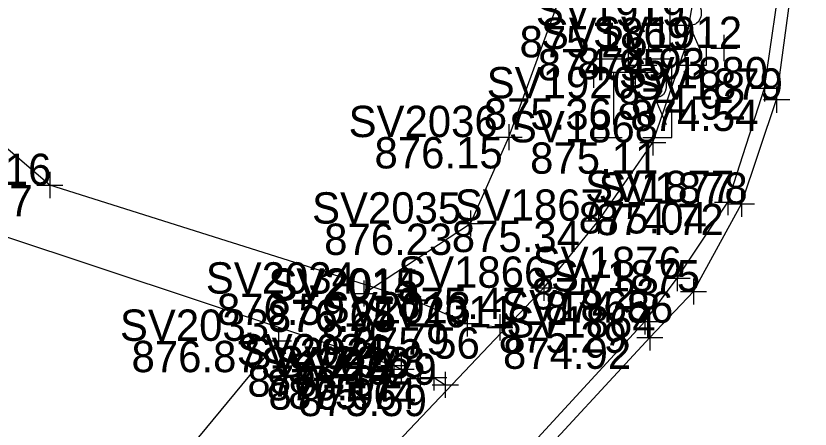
# Model space of a CAD drawing. Extents: x 1480001 to 1480402, y 379235 to 379603.
# Drawn here: x 1480114.39 to 1480144.8, y 379390.17 to 379405.99 of the extents above; entities that cross this region are included whole.
import ezdxf

# ---------------------------------------------------------------- set-up
doc = ezdxf.new("R2010")
doc.units = 0
for name, color, linetype in [('PV_X_Curb', 7, 'Continuous'), ('PV_X_Walk', 7, 'Continuous'), ('SG_X_PullBox', 7, 'Continuous'), ('SV_X_Break_Lines', 7, 'Continuous'), ('SV_X_Shot_Marker', 7, 'Continuous'), ('SV_X_Text_Elevation', 7, 'Continuous'), ('SV_X_Text_Name', 7, 'Continuous')]:
    doc.layers.add(name, color=color, linetype=linetype)

msp = doc.modelspace()

# ---------------------------------------------------------------- linework, layer by layer
at = {"layer": 'PV_X_Curb'}
for points in [[(1480097.622, 379349.287), (1480115.163, 379368.135), (1480120.989, 379374.507), (1480122.913, 379376.573), (1480123.248, 379376.579), (1480124.233, 379378.045), (1480138.666, 379393.676), (1480140.342, 379395.44), (1480142.173, 379398.797), (1480143.522, 379402.786), (1480144.219, 379407.995), (1480144.4, 379409.609), (1480144.536, 379411.589), (1480144.804, 379414.142), (1480144.365, 379416.981), (1480143.824, 379419.476), (1480142.93, 379422.24), (1480141.664, 379424.24), (1480139.564, 379427.9), (1480137.133, 379430.292), (1480135.19, 379432.332), (1480118.45, 379448.16)], [(1480097.272, 379349.731), (1480114.906, 379368.678), (1480120.582, 379374.885), (1480122.682, 379377.153), (1480124.005, 379378.548), (1480138.475, 379394.29), (1480139.717, 379395.951), (1480141.648, 379398.861), (1480143.063, 379403.22), (1480143.762, 379408.065), (1480143.873, 379409.698), (1480144.124, 379411.499), (1480144.338, 379414.245), (1480144.085, 379416.674), (1480143.405, 379419.529), (1480142.307, 379421.83), (1480141.33, 379424.009), (1480139.247, 379427.506), (1480136.787, 379429.98), (1480135, 379431.897), (1480118.039, 379447.914)]]:
    msp.add_lwpolyline(points, dxfattribs=at)
at = {"layer": 'PV_X_Walk'}
for points in [[(1480035.484, 379289.224), (1480050.568, 379305.437), (1480062.335, 379317.896), (1480064.038, 379319.719), (1480070.805, 379327.066), (1480078.054, 379334.946), (1480079.953, 379336.866), (1480094.208, 379352.393), (1480112.048, 379371.575), (1480117.348, 379377.211), (1480119.911, 379379.906), (1480121.511, 379381.77), (1480134.604, 379395.58), (1480136.695, 379398.148), (1480138.778, 379401.149), (1480140.004, 379404.725), (1480140.577, 379408.06), (1480140.982, 379411.311), (1480140.871, 379414.584), (1480140.225, 379417.636), (1480139.184, 379419.586), (1480133.124, 379425.845), (1480132.903, 379425.968), (1480114.834, 379442.96)], [(1480132.927, 379394.064), (1480131.678, 379394.217), (1480129.623, 379395.124), (1480129.685, 379395.088), (1480115.69, 379399.516), (1480110.694, 379403.782)], [(1480103.907, 379387.432), (1480113.836, 379397.599), (1480128.867, 379392.608), (1480129.145, 379392.467), (1480129.878, 379392.11), (1480130.393, 379392.142), (1480130.835, 379391.865)]]:
    msp.add_lwpolyline(points, dxfattribs=at)
at = {"layer": 'SG_X_PullBox'}
for p, q in [((1480139.337, 379405.608), (1480139.337, 379405.608)), ((1480138.004, 379402.836), (1480138.004, 379402.836))]:
    msp.add_line(p, q, dxfattribs=at)
for points in [[(1480138.611, 379406.608), (1480138.611, 379404.608)], [(1480139.449, 379404.608), (1480139.449, 379406.608), (1480140.205, 379406.608), (1480140.283, 379406.592), (1480140.394, 379406.56), (1480140.441, 379406.529), (1480140.488, 379406.497), (1480140.551, 379406.419), (1480140.598, 379406.34), (1480140.63, 379406.214), (1480140.63, 379406.025), (1480140.614, 379405.962), (1480140.583, 379405.868), (1480140.52, 379405.757), (1480140.457, 379405.71), (1480140.409, 379405.679), (1480140.378, 379405.663), (1480140.331, 379405.647), (1480140.189, 379405.631), (1480139.449, 379405.631)], [(1480140.189, 379405.631), (1480140.63, 379404.608)], [(1480137.837, 379405.208), (1480137.837, 379404.108), (1480138.937, 379404.108)], [(1480139.737, 379404.108), (1480140.837, 379404.108), (1480140.837, 379405.208)], [(1480137.604, 379404.336), (1480136.504, 379404.336), (1480136.504, 379403.236)], [(1480139.504, 379403.236), (1480139.504, 379404.336), (1480138.404, 379404.336)], [(1480136.648, 379403.836), (1480137.892, 379403.836)], [(1480137.278, 379403.836), (1480137.278, 379401.836)], [(1480138.116, 379401.836), (1480138.116, 379403.836), (1480138.872, 379403.836), (1480138.95, 379403.82), (1480139.061, 379403.789), (1480139.108, 379403.757), (1480139.155, 379403.726), (1480139.218, 379403.647), (1480139.265, 379403.568), (1480139.297, 379403.442), (1480139.297, 379403.253), (1480139.281, 379403.19), (1480139.25, 379403.096), (1480139.187, 379402.985), (1480139.124, 379402.938), (1480139.076, 379402.907), (1480139.045, 379402.891), (1480138.998, 379402.875), (1480138.856, 379402.859), (1480138.116, 379402.859)], [(1480138.856, 379402.859), (1480139.297, 379401.836)], [(1480136.504, 379402.436), (1480136.504, 379401.336), (1480137.604, 379401.336)], [(1480138.404, 379401.336), (1480139.504, 379401.336), (1480139.504, 379402.436)]]:
    msp.add_lwpolyline(points, dxfattribs=at)
at = {"layer": 'SV_X_Break_Lines'}
for points in [[(1480127.721, 379395.358), (1480131.799, 379398.039), (1480133.273, 379401.352), (1480135.459, 379407.36), (1480135.6, 379409.555), (1480135.793, 379413.076), (1480135.014, 379415.657), (1480133.026, 379417.684), (1480123.803, 379426.624), (1480113.121, 379435.343), (1480106.984, 379440.926), (1480103.73, 379443.918), (1480102.529, 379445.074), (1480100.774, 379445.951), (1480096.595, 379444.059), (1480092.174, 379441.029), (1480086.377, 379436.591)], [(1480102.555, 379367.391), (1480110.126, 379376.156), (1480117.553, 379385.207), (1480124.442, 379393.548)]]:
    msp.add_lwpolyline(points, dxfattribs=at)
at = {"layer": 'SV_X_Shot_Marker'}
for p, q in [((1480140.004, 379405.225), (1480140.004, 379404.225)), ((1480141.506, 379405.264), (1480141.506, 379404.264)), ((1480139.504, 379404.725), (1480140.504, 379404.725)), ((1480140.004, 379404.725), (1480140.004, 379404.725)), ((1480141.006, 379404.764), (1480142.006, 379404.764)), ((1480141.506, 379404.764), (1480141.506, 379404.764)), ((1480143.063, 379403.72), (1480143.063, 379402.72)), ((1480142.563, 379403.22), (1480143.563, 379403.22)), ((1480143.063, 379403.22), (1480143.063, 379403.22)), ((1480143.522, 379403.286), (1480143.522, 379402.286)), ((1480143.022, 379402.786), (1480144.022, 379402.786)), ((1480143.522, 379402.786), (1480143.522, 379402.786)), ((1480133.273, 379401.852), (1480133.273, 379400.852)), ((1480138.778, 379401.649), (1480138.778, 379400.649)), ((1480132.773, 379401.352), (1480133.773, 379401.352)), ((1480133.273, 379401.352), (1480133.273, 379401.352)), ((1480138.278, 379401.149), (1480139.278, 379401.149)), ((1480138.778, 379401.149), (1480138.778, 379401.149)), ((1480115.69, 379400.016), (1480115.69, 379399.016)), ((1480115.19, 379399.516), (1480116.19, 379399.516)), ((1480115.69, 379399.516), (1480115.69, 379399.516)), ((1480141.648, 379399.361), (1480141.648, 379398.361)), ((1480142.173, 379399.297), (1480142.173, 379398.297)), ((1480141.148, 379398.861), (1480142.148, 379398.861)), ((1480141.648, 379398.861), (1480141.648, 379398.861)), ((1480131.799, 379398.539), (1480131.799, 379397.539)), ((1480136.695, 379398.648), (1480136.695, 379397.648)), ((1480141.673, 379398.797), (1480142.673, 379398.797)), ((1480142.173, 379398.797), (1480142.173, 379398.797)), ((1480131.299, 379398.039), (1480132.299, 379398.039)), ((1480131.799, 379398.039), (1480131.799, 379398.039)), ((1480136.195, 379398.148), (1480137.195, 379398.148)), ((1480136.695, 379398.148), (1480136.695, 379398.148)), ((1480139.717, 379396.451), (1480139.717, 379395.451)), ((1480134.604, 379396.08), (1480134.604, 379395.08)), ((1480127.721, 379395.858), (1480127.721, 379394.858)), ((1480139.217, 379395.951), (1480140.217, 379395.951)), ((1480139.717, 379395.951), (1480139.717, 379395.951)), ((1480140.342, 379395.94), (1480140.342, 379394.94)), ((1480129.623, 379395.624), (1480129.623, 379394.624)), ((1480129.685, 379395.588), (1480129.685, 379394.588)), ((1480134.104, 379395.58), (1480135.104, 379395.58)), ((1480134.604, 379395.58), (1480134.604, 379395.58)), ((1480127.221, 379395.358), (1480128.221, 379395.358)), ((1480127.721, 379395.358), (1480127.721, 379395.358)), ((1480139.842, 379395.44), (1480140.842, 379395.44)), ((1480140.342, 379395.44), (1480140.342, 379395.44)), ((1480129.123, 379395.124), (1480130.123, 379395.124)), ((1480129.185, 379395.088), (1480130.185, 379395.088)), ((1480129.623, 379395.124), (1480129.623, 379395.124)), ((1480129.685, 379395.088), (1480129.685, 379395.088)), ((1480131.678, 379394.717), (1480131.678, 379393.717)), ((1480132.927, 379394.564), (1480132.927, 379393.564)), ((1480138.475, 379394.79), (1480138.475, 379393.79)), ((1480137.975, 379394.29), (1480138.975, 379394.29)), ((1480138.475, 379394.29), (1480138.475, 379394.29)), ((1480124.442, 379394.048), (1480124.442, 379393.048)), ((1480131.178, 379394.217), (1480132.178, 379394.217)), ((1480131.678, 379394.217), (1480131.678, 379394.217)), ((1480132.427, 379394.064), (1480133.427, 379394.064)), ((1480132.927, 379394.064), (1480132.927, 379394.064)), ((1480138.666, 379394.176), (1480138.666, 379393.176)), ((1480138.166, 379393.676), (1480139.166, 379393.676)), ((1480138.666, 379393.676), (1480138.666, 379393.676)), ((1480123.942, 379393.548), (1480124.942, 379393.548)), ((1480124.442, 379393.548), (1480124.442, 379393.548)), ((1480128.867, 379393.108), (1480128.867, 379392.108)), ((1480129.145, 379392.967), (1480129.145, 379391.967)), ((1480128.367, 379392.608), (1480129.367, 379392.608)), ((1480128.645, 379392.467), (1480129.645, 379392.467)), ((1480128.867, 379392.608), (1480128.867, 379392.608)), ((1480129.145, 379392.467), (1480129.145, 379392.467)), ((1480129.878, 379392.61), (1480129.878, 379391.61)), ((1480130.393, 379392.642), (1480130.393, 379391.642)), ((1480129.893, 379392.142), (1480130.893, 379392.142)), ((1480130.393, 379392.142), (1480130.393, 379392.142)), ((1480130.835, 379392.365), (1480130.835, 379391.365)), ((1480129.378, 379392.11), (1480130.378, 379392.11)), ((1480129.878, 379392.11), (1480129.878, 379392.11)), ((1480130.335, 379391.865), (1480131.335, 379391.865)), ((1480130.835, 379391.865), (1480130.835, 379391.865))]:
    msp.add_line(p, q, dxfattribs=at)

# ---------------------------------------------------------------- texts
at = {"layer": 'SV_X_Text_Elevation'}
for s, p in [('875.26', (1480133.678, 379404.408)), ('874.95', (1480134.373, 379403.525)), ('874.93', (1480135.875, 379403.564)), ('874.92', (1480137.441, 379402.02)), ('875.36', (1480132.307, 379401.636)), ('874.54', (1480137.919, 379401.586)), ('876.15', (1480128.124, 379400.152)), ('875.11', (1480134.082, 379399.949)), ('877.27', (1480110.125, 379398.316)), ('875.04', (1480135.941, 379397.661)), ('874.72', (1480136.589, 379397.597)), ('876.23', (1480126.196, 379396.839)), ('875.34', (1480131.083, 379396.948)), ('875.23', (1480134.133, 379394.751)), ('875.47', (1480128.992, 379394.38)), ('876.59', (1480122.09, 379394.158)), ('874.86', (1480134.654, 379394.24)), ('876.24', (1480124.03, 379393.924)), ('876.65', (1480124.044, 379393.888)), ('875.29', (1480132.882, 379393.09)), ('875.79', (1480126.085, 379393.017)), ('875.56', (1480127.249, 379392.864)), ('874.92', (1480133.044, 379392.476)), ('876.87', (1480118.82, 379392.348)), ('876.79', (1480123.255, 379391.408)), ('876.17', (1480123.996, 379391.267)), ('876.06', (1480124.067, 379390.91)), ('875.74', (1480124.819, 379390.942)), ('875.59', (1480125.223, 379390.665))]:
    msp.add_text(s, height=1.2, dxfattribs=at).set_placement(p)
at = {"layer": 'SV_X_Text_Name'}
for s, p in [('SV1919', (1480134.302, 379405.608)), ('SV1869', (1480134.496, 379404.725)), ('SV1912', (1480136.49, 379404.764)), ('SV1880', (1480137.48, 379403.22)), ('SV1920', (1480132.421, 379402.836)), ('SV1879', (1480138.052, 379402.786)), ('SV2036', (1480127.132, 379401.352)), ('SV1868', (1480133.27, 379401.149)), ('SV2016', (1480110.041, 379399.516)), ('SV1877', (1480136.188, 379398.861)), ('SV1878', (1480136.703, 379398.797)), ('SV2035', (1480125.733, 379398.039)), ('SV1867', (1480131.197, 379398.148)), ('SV1876', (1480134.181, 379395.951)), ('SV1866', (1480129.03, 379395.58)), ('SV2034', (1480121.665, 379395.358)), ('SV1875', (1480134.882, 379395.44)), ('SV2014', (1480124.059, 379395.124)), ('SV2015', (1480124.111, 379395.088)), ('SV1865', (1480132.977, 379394.29)), ('SV2013', (1480126.104, 379394.217)), ('SV2011', (1480127.787, 379394.064)), ('SV1864', (1480133.177, 379393.676)), ('SV2033', (1480118.376, 379393.548)), ('SV2024', (1480122.849, 379392.608)), ('SV2025', (1480123.117, 379392.467)), ('SV2028', (1480124.356, 379392.142)), ('SV2026', (1480123.775, 379392.11)), ('SV2029', (1480124.798, 379391.865))]:
    msp.add_text(s, height=1.2, dxfattribs=at).set_placement(p)

doc.saveas('drawing.dxf')
